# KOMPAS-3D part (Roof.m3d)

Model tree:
1. Plane XY
2. Plane ZX
3. Plane ZY
4. X Axis
5. Y Axis
6. Z Axis
7. Origin
8. Sketch:1
9. Extrude:1
     Wall Thickness 1 = 1; Wall Thickness 2 = 1; Distance 1 = 10; Distance 2 = 12640

Referenced files in D:\Documents and Settings\kashirsky\Рабочий стол\Cottage\: Cottage.a3d
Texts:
  Steel DIN 17102
  Three Point Plane
  Plane at Angle
  Line and Point Plane
  Axis through Two Vertices
  Axis of Feature
  Axis of Conical Surface
  Axis through Edge
  Trim by Surface
  Trim by Sketch
  Feature with No History
  Intersection Axis of Two Planes
  Two Line Plane
  Line and Face Plane
  Bend by line
  Hole in sheet body
  Cut in sheet body
  Point in CM
  Linear Dimension from Line to Point
  Surface Finish Symbol
  Geometric Tolerance Symbol
  Leader #1
  Leader #2
  Leader #3
  Shape Deviations and Datum
  Node point number
  Mark of coordination axis
  Node point designation
  Mark/Reference designation with leader
  Mark/reference designation on line
  Mark/Reference designation without leader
